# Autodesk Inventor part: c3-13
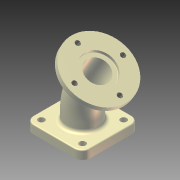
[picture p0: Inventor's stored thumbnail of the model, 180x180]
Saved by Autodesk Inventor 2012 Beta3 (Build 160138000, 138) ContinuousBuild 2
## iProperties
Created: 2010-11
Part Number: c3-13
Material: Cast Iron
Document SubType Name: Modeling
Designer: Beta-8540w
Density: 7.25 g/cm^3
Mass: 1087.5 g
Surface Area: 260 cm^2
Volume: 150 cm^3
Author: Beta-8540w
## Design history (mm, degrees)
sketch "Sketch1"
  geometry: L1 (-50, -50)-(50, -50); L2 (50, -50)-(50, 50); L3 (50, 50)-(-50, 50); L4 (-50, 50)-(-50, -50); C1 r 20 at (0, 0); C2 r 28 at (0, 0); 3 further points
  constraints: 8 end point, 3 perpendicular, 2 centre point, 2 coincident, 2 midpoint, 1 horizontal, 1 horizontal alignment, 1 parallel, 1 vertical alignment
  dimensions: "Width" = 100 distance of L1.start L1.end; "d6" = 40 diameter of C1; "d7" = 8 radial gap between concentric circles of C2 C1
extrude "Extrusion1" new body sketch "Sketch1" distance "d3" = 15; taper "d4" = 0 deg
fillet "Fillet1" dims "d5" = 14
sketch "Sketch2"
  geometry: L1 (0, 0)-(0, 30); L2 (-13.397, 80)-(-28.397, 105.981); A1 r 100 centre (-100, 30) between (0, 30) and (-13.397, 80)
  constraints: 4 end point, 2 point on circle, 2 tangent, 1 centre point, 1 vertical
  dimensions: "d8" = 30 distance of L1.start L1.end; "d9" = 100 radius of A1; "d10" = 30 distance of L2.start L2.end; "d11" = 30 deg angle of L2 L1
sketch "Sketch3"
  geometry: L1 (-13.397, 80)-(-28.397, 105.981) reference; L2 (-28.397, 105.981)-(-76.029, 78.481); L3 (-76.029, 78.481)-(-71.029, 69.821); L4 (-71.029, 69.821)-(-23.397, 97.321); L5 (-23.397, 97.321)-(-28.397, 105.981); 1 further point
  constraints: 8 end point, 2 parallel, 2 perpendicular
  dimensions: "d16" = 10 distance of L3.end L2.end; "d17" = 110 diameter of L3 L5
revolve "Revolution1" sketch "Sketch3" stored, may be unused: angle "d18" = 90 deg
sweep "Sweep1" dims "d19" = 0
sweep "Sweep2" dims "d20" = 0
sketch "Sketch4"
  geometry: C1 r 20 at (0, 0) reference; C2 r 55 at (0, 0) reference; C3 r 27.5 at (0, 0); 1 further point
  constraints: 1 centre point, 1 coincident
  dimensions: "d21" = 55 diameter of C3
extrude "Extrusion2" cut sketch "Sketch4" distance "d22" = 5; taper "d23" = 0 deg
sketch "Sketch5"
  geometry: L1 (0, 0)-(0, 9.711); L2 (-25, 0)-(-27, 0); L3 (-27, 0)-(-27, 1.5); L4 (-26.5, 2)-(-25.5, 2); L5 (-25, 1.5)-(-25, 0); A1 r 0.5 centre (-25.5, 1.5) between (-25, 1.5) and (-25.5, 2); A2 r 0.5 centre (-26.5, 1.5) between (-26.5, 2) and (-27, 1.5); 1 further point
  constraints: 10 end point, 4 point on circle, 4 tangent, 3 point on line, 2 centre point, 2 parallel, 1 equal radius, 1 horizontal, 1 perpendicular, 1 vertical
  dimensions: "d24" = 2 distance of L2.start L2.end; "d25" = 2 distance of point (-25, 2) L2.start; "d26" = 50 diameter of L5 L1; "d27" = 0.5 radius of A1
revolve "Revolution2" sketch "Sketch5" stored, may be unused: angle "d28" = 90 deg
hole "Hole1" diameter "d31" = 11; stored, may be unused: countersink angle "d35" = 7.5 deg, drill point angle "d37" = 118 deg; dims "d29" = 10, "d30" = 10, "d32" = 6, "d33" = 28, "d34" = 2, "d36" = 8
pattern_circular "Circular Pattern1" dims angle "d39" = 360 deg
sketch "Hole Sketch" dims "d41" = 85
  geometry: L1 (0, -42.5)-(-42.5, 0); L2 (-42.5, 0)-(0, 42.5); L3 (0, 42.5)-(42.5, 0); L4 (42.5, 0)-(0, -42.5); C1 r 27.5 at (0, 0) reference; 2 further points
  constraints: 8 end point, 2 coincident, 2 horizontal alignment, 11 other
hole "Hole2" sketch "Hole Sketch" at (0, -42.5), (-42.5, 0), (0, 42.5), (42.5, 0) diameter "d42" = 8.376; stored, may be unused: countersink angle "d46" = 90 deg, drill point angle "d48" = 118 deg; dims "d43" = 6, "d44" = 4, "d45" = 2, "d47" = 8
fillet "Fillet2" dims "d49" = 6, "d50" = 2, "d51" = 0.5
body "Solid1"
